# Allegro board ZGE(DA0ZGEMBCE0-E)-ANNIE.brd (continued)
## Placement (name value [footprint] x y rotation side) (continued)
CG570  0.47u/6.3V_2  [C0201]  64.07 113.05 90 bottom
CG571  0.47u/6.3V_2  [C0201]  62.64 113.05 270 bottom
CG572  0.47u/6.3V_2  [C0201]  63.36 113.05 90 bottom
CG573  0.47u/6.3V_2  [C0201]  61.93 113.05 270 bottom
CG574  0.47u/6.3V_2  [C0201]  22.87 113.01 180 bottom
CG575  330u/2V_7343H1.9  [CC7343]  83.44 112.99 90 bottom
CG576  0.47u/6.3V_2  [C0201]  56.79 112.93 0 bottom
CG577  0.47u/6.3V_2  [C0201]  21.84 112.87 270 bottom
CG578  47u/6.3V_8  [C0805]  59.22 112.81 180 bottom
CG579  0.47u/6.3V_2  [C0201]  66.09 112.65 180 bottom
CG580  0.47u/6.3V_2  [C0201]  55.48 112.56 0 bottom
CG581  0.47u/6.3V_2  [C0201]  65.11 112.52 180 bottom
CG582  0.47u/6.3V_2  [C0201]  44.72 112.3 180 bottom
CG583  0.47u/6.3V_2  [C0201]  14.06 112.16 180 bottom
CG584  0.47u/6.3V_2  [C0201]  24.5 111.99 270 bottom
CG585  10u/6.3V_6  [C0603]  99.17 111.98 0 bottom
CG586  0.47u/6.3V_2  [C0201]  9.92 111.87 270 bottom
CG587  22u/6.3V_6  [C0603]  8.65 111.85 90 bottom
CG588  0.47u/6.3V_2  [C0201]  87.72 111.73 0 bottom
CG589  0.47u/6.3V_2  [C0201]  95.55 111.71 180 bottom
CG590  0.47u/6.3V_2  [C0201]  47.61 111.7 270 bottom
CG591  0.47u/6.3V_2  [C0201]  46.89 111.7 90 bottom
CG592  0.47u/6.3V_2  [C0201]  46.15 111.7 270 bottom
CG593  0.47u/6.3V_2  [C0201]  96.93 111.7 0 bottom
CG594  0.47u/6.3V_2  [C0201]  48.32 111.7 270 bottom
CG595  0.47u/6.3V_2  [C0201]  51.89 111.7 270 bottom
CG596  0.47u/6.3V_2  [C0201]  49.75 111.7 90 bottom
CG597  0.47u/6.3V_2  [C0201]  51.18 111.7 90 bottom
CG598  0.47u/6.3V_2  [C0201]  50.46 111.7 270 bottom
CG599  0.47u/6.3V_2  [C0201]  49.04 111.7 90 bottom
CG600  0.47u/6.3V_2  [C0201]  52.61 111.7 90 bottom
CG601  0.47u/6.3V_2  [C0201]  53.33 111.69 270 bottom
CG602  0.47u/6.3V_2  [C0201]  63.71 111.68 270 bottom
CG603  0.47u/6.3V_2  [C0201]  63 111.68 270 bottom
CG604  0.47u/6.3V_2  [C0201]  62.28 111.68 90 bottom
CG605  0.47u/6.3V_2  [C0201]  61.57 111.68 90 bottom
CG606  0.47u/6.3V_2  [C0201]  54.04 111.68 270 bottom
CG607  0.47u/6.3V_2  [C0201]  55.47 111.68 270 bottom
CG608  0.47u/6.3V_2  [C0201]  54.76 111.68 90 bottom
CG609  0.47u/6.3V_2  [C0201]  56.18 111.67 90 bottom
CG610  0.47u/6.3V_2  [C0201]  56.9 111.65 90 bottom
CG611  0.47u/6.3V_2  [C0201]  19.59 111.62 270 bottom
CG612  0.47u/6.3V_2  [C0201]  14.95 111.6 270 bottom
CG613  0.47u/6.3V_2  [C0201]  57.76 111.47 180 bottom
CG614  0.47u/6.3V_2  [C0201]  59.73 111.46 180 bottom
CG615  0.47u/6.3V_2  [C0201]  58.74 111.46 0 bottom
CG616  0.47u/6.3V_2  [C0201]  60.72 111.46 0 bottom
CG617  10u/6.3V_6  [C0603]  65.38 111.3 0 bottom
CG618  22u/6.3V_6  [C0603]  44.19 111.22 180 bottom
CG619  0.47u/6.3V_2  [C0201]  89.41 111.12 0 bottom
CG620  0.47u/6.3V_2  [C0201]  18.12 111.01 180 bottom
CG621  0.47u/6.3V_2  [C0201]  90.93 110.94 180 bottom
CG622  0.47u/6.3V_2  [C0201]  86.35 110.91 0 bottom
CG623  22u/6.3V_6  [C0603]  25.44 110.76 0 bottom
CG624  0.47u/6.3V_2  [C0201]  99.95 110.61 270 bottom
CG625  0.47u/6.3V_2  [C0201]  49.27 110.31 270 bottom
CG626  0.47u/6.3V_2  [C0201]  48.55 110.3 90 bottom
CG627  0.47u/6.3V_2  [C0201]  60.95 110.3 90 bottom
CG628  0.47u/6.3V_2  [C0201]  49.99 110.29 270 bottom
CG629  0.47u/6.3V_2  [C0201]  60.24 110.29 90 bottom
CG630  10u/6.3V_6  [C0603]  46.87 110.29 0 bottom
CG631  0.47u/6.3V_2  [C0201]  59.53 110.29 270 bottom
CG632  0.47u/6.3V_2  [C0201]  58.81 110.29 270 bottom
CG633  10u/6.3V_6  [C0603]  51.67 110.29 180 bottom
CG634  0.47u/6.3V_2  [C0201]  55.48 110.27 90 bottom
CG635  0.47u/6.3V_2  [C0201]  54.76 110.27 270 bottom
CG636  10u/6.3V_6  [C0603]  62.62 110.27 0 bottom
CG637  0.47u/6.3V_2  [C0201]  53.34 110.27 90 bottom
CG638  0.47u/6.3V_2  [C0201]  54.05 110.27 90 bottom
CG639  10u/6.3V_6  [C0603]  57.15 110.26 0 bottom
CG640  0.47u/6.3V_2  [C0201]  66.65 110.24 180 bottom
CG641  0.47u/6.3V_2  [C0201]  65.2 110.23 180 bottom
CG642  0.47u/6.3V_2  [C0201]  44.94 110.16 180 bottom
CG643  0.47u/6.3V_2  [C0201]  43.6 110.15 0 bottom
CG644  22u/6.3V_6  [C0603]  72.17 109.48 270 bottom
CG645  0.47u/6.3V_2  [C0201]  18.79 109.47 0 bottom
CG646  0.47u/6.3V_2  [C0201]  44.95 109.44 180 bottom
CG647  0.47u/6.3V_2  [C0201]  43.6 109.43 0 bottom
CG648  0.47u/6.3V_2  [C0201]  23.81 109.4 90 bottom
CG649  10u/6.3V_6  [C0603]  65.36 109.17 180 bottom
CG650  0.47u/6.3V_2  [C0201]  45.85 108.91 90 bottom
CG651  0.47u/6.3V_2  [C0201]  47.99 108.91 90 bottom
CG652  0.47u/6.3V_2  [C0201]  47.27 108.91 270 bottom
CG653  0.47u/6.3V_2  [C0201]  48.7 108.91 270 bottom
CG654  0.47u/6.3V_2  [C0201]  55.84 108.91 90 bottom
CG655  0.47u/6.3V_2  [C0201]  52.99 108.91 90 bottom
CG656  0.47u/6.3V_2  [C0201]  46.56 108.91 270 bottom
CG657  0.47u/6.3V_2  [C0201]  55.13 108.91 90 bottom
CG658  0.47u/6.3V_2  [C0201]  54.41 108.91 270 bottom
CG659  0.47u/6.3V_2  [C0201]  53.7 108.91 270 bottom
CG660  0.47u/6.3V_2  [C0201]  57.27 108.91 270 bottom
CG661  0.47u/6.3V_2  [C0201]  56.55 108.91 90 bottom
CG662  0.47u/6.3V_2  [C0201]  52.27 108.91 270 bottom
CG663  0.47u/6.3V_2  [C0201]  51.56 108.91 90 bottom
CG664  0.47u/6.3V_2  [C0201]  60.12 108.9 270 bottom
CG665  0.47u/6.3V_2  [C0201]  59.41 108.9 270 bottom
CG666  0.47u/6.3V_2  [C0201]  50.85 108.9 270 bottom
CG667  0.47u/6.3V_2  [C0201]  58.7 108.9 90 bottom
CG668  0.47u/6.3V_2  [C0201]  57.98 108.9 270 bottom
CG669  0.47u/6.3V_2  [C0201]  49.42 108.9 270 bottom
CG670  0.47u/6.3V_2  [C0201]  50.14 108.9 90 bottom
CG671  0.47u/6.3V_2  [C0201]  63.69 108.9 270 bottom
CG672  0.47u/6.3V_2  [C0201]  62.97 108.9 270 bottom
CG673  0.47u/6.3V_2  [C0201]  62.26 108.9 90 bottom
CG674  0.47u/6.3V_2  [C0201]  61.54 108.9 270 bottom
CG675  0.47u/6.3V_2  [C0201]  60.83 108.9 270 bottom
CG676  0.47u/6.3V_2  [C0201]  90.87 108.86 180 bottom
CG677  0.47u/6.3V_2  [C0201]  14.23 108.7 0 bottom
CG678  0.47u/6.3V_2  [C0201]  18.78 108.58 0 bottom
CG679  10u/6.3V_6  [C0603]  26.79 108.58 90 bottom
CG680  10u/6.3V_6  [C0603]  24.66 108.14 180 bottom
CG681  0.47u/6.3V_2  [C0201]  65.13 108.11 180 bottom
CG682  0.47u/6.3V_2  [C0201]  90.14 108.09 0 bottom
CG683  0.47u/6.3V_2  [C0201]  22.77 108.08 180 bottom
CG684  0.47u/6.3V_2  [C0201]  20.82 108.08 0 bottom
CG685  0.47u/6.3V_2  [C0201]  94.82 108.07 90 bottom
CG686  0.47u/6.3V_2  [C0201]  15.49 108.07 180 bottom
CG687  0.47u/6.3V_2  [C0201]  12.37 108.05 0 bottom
CG688  0.47u/6.3V_2  [C0201]  10.73 108 0 bottom
CG689  47u/6.3V_8  [C0805]  43.88 107.82 0 bottom
CG690  1u/6.3V_2  [C0201]  84.83 107.66 270 bottom
CG691  0.47u/6.3V_2  [C0201]  99.62 107.54 90 bottom
CG692  10u/6.3V_6  [C0603]  47.63 107.51 0 bottom
CG693  0.47u/6.3V_2  [C0201]  59.7 107.5 270 bottom
CG694  0.47u/6.3V_2  [C0201]  58.98 107.5 90 bottom
CG695  10u/6.3V_6  [C0603]  53.12 107.49 180 bottom
CG696  0.47u/6.3V_2  [C0201]  49.3 107.48 90 bottom
CG697  0.47u/6.3V_2  [C0201]  50.02 107.48 270 bottom
CG698  0.47u/6.3V_2  [C0201]  45.94 107.47 270 bottom
CG699  0.47u/6.3V_2  [C0201]  50.73 107.46 90 bottom
CG700  0.47u/6.3V_2  [C0201]  51.44 107.45 270 bottom
CG701  0.47u/6.3V_2  [C0201]  97.9 107.34 180 bottom
CG702  *820p/50V_4  [C0402]  17.21 107.18 180 bottom
CG703  10u/6.3V_6  [C0603]  65.28 107.04 180 bottom
CG704  10u/6.3V_6  [C0603]  11.75 106.9 180 bottom
CG705  10u/6.3V_6  [C0603]  56.2 106.73 90 bottom
CG706  10u/6.3V_6  [C0603]  57.62 106.73 90 bottom
CG707  0.47u/6.3V_2  [C0201]  86.93 106.71 0 bottom
CG708  *22u/6.3V_6  [C0603]  62.87 106.58 270 bottom
CG709  *22u/6.3V_6  [C0603]  61.04 106.58 270 bottom
CG710  0.47u/6.3V_2  [C0201]  43.7 106.42 0 bottom
CG711  0.47u/6.3V_2  [C0201]  97.38 106.34 90 bottom
CG712  0.47u/6.3V_2  [C0201]  88.06 106.33 90 bottom
CG713  2.2u/10V_4  [C0402]  24.58 106.16 90 bottom
CG714  0.47u/6.3V_2  [C0201]  54.08 106.11 90 bottom
CG715  0.47u/6.3V_2  [C0201]  53.36 106.11 270 bottom
CG716  0.47u/6.3V_2  [C0201]  52.64 106.11 90 bottom
CG717  0.47u/6.3V_2  [C0201]  47.87 106.11 90 bottom
CG718  0.47u/6.3V_2  [C0201]  48.58 106.11 90 bottom
CG719  0.47u/6.3V_2  [C0201]  49.3 106.1 270 bottom
CG720  0.47u/6.3V_2  [C0201]  59.7 106.1 90 bottom
CG721  0.47u/6.3V_2  [C0201]  58.98 106.1 270 bottom
CG722  22u/6.3V_6  [C0603]  50.97 106.07 0 bottom
CG723  0.47u/6.3V_2  [C0201]  96.38 105.99 90 bottom
CG724  0.47u/6.3V_2  [C0201]  64.59 105.98 180 bottom
CG725  47u/6.3V_8  [C0805]  45.89 105.72 180 bottom
CG726  22u/6.3V_6  [C0603]  99.3 105.71 270 bottom
CG727  4.7u/6.3V_6  [C0603]  86.2 105.64 180 bottom
CG728  0.47u/6.3V_2  [C0201]  43.78 105.61 0 bottom
CG729  0.1u/16V_4  [C0402]  18.14 105.18 0 bottom
CG730  0.47u/6.3V_2  [C0201]  97.95 104.91 180 bottom
CG731  10u/6.3V_6  [C0603]  65.27 104.9 0 bottom
CG732  0.47u/6.3V_2  [C0201]  59.7 104.7 270 bottom
CG733  0.47u/6.3V_2  [C0201]  58.98 104.7 90 bottom
CG734  0.47u/6.3V_2  [C0201]  93.02 104.48 270 bottom
CG735  0.47u/6.3V_2  [C0201]  96.34 104.33 270 bottom
CG736  47u/6.3V_8  [C0805]  49.3 104.3 0 bottom
CG737  4.7u/6.3V_6  [C0603]  39.24 104.17 90 bottom
CG738  10u/6.3V_6  [C0603]  37.61 104.17 90 bottom
CG739  4.7u/6.3V_6  [C0603]  40.67 104.15 270 bottom
CG740  0.47u/6.3V_2  [C0201]  87.58 104.15 0 bottom
CG741  0.47u/6.3V_2  [C0201]  46.6 104.02 270 bottom
CG742  0.47u/6.3V_2  [C0201]  47.32 104.02 270 bottom
CG743  0.47u/6.3V_2  [C0201]  45.89 104.02 90 bottom
CG744  0.47u/6.3V_2  [C0201]  19.07 103.8 0 bottom
CG745  0.47u/6.3V_2  [C0201]  99.74 103.79 270 bottom
CG746  0.47u/6.3V_2  [C0201]  64.39 103.69 270 bottom
CG747  0.47u/6.3V_2  [C0201]  90.93 103.65 0 bottom
CG748  0.47u/6.3V_2  [C0201]  89.96 103.62 270 bottom
CG749  10u/6.3V_6  [C0603]  62.53 103.57 90 bottom
CG750  22u/6.3V_6  [C0603]  61.09 103.57 90 bottom
CG751  10u/6.3V_6  [C0603]  56.2 103.57 270 bottom
CG752  10u/6.3V_6  [C0603]  57.62 103.56 270 bottom
CG753  0.47u/6.3V_2  [C0201]  84.75 103.37 90 bottom
CG754  0.47u/6.3V_2  [C0201]  59.7 103.3 270 bottom
CG755  0.47u/6.3V_2  [C0201]  58.98 103.3 90 bottom
CG756  22u/6.3V_6  [C0603]  43.4 103.13 90 bottom
CG757  4.7u/6.3V_6  [C0603]  44.82 103.13 270 bottom
CG758  10u/6.3V_6  [C0603]  65.34 102.77 225 bottom
CG759  0.47u/6.3V_2  [C0201]  52.64 102.61 90 bottom
CG760  0.47u/6.3V_2  [C0201]  51.93 102.61 90 bottom
CG761  0.47u/6.3V_2  [C0201]  51.22 102.61 270 bottom
CG762  0.47u/6.3V_2  [C0201]  48.36 102.61 90 bottom
CG763  0.47u/6.3V_2  [C0201]  47.65 102.61 270 bottom
CG764  0.47u/6.3V_2  [C0201]  53.36 102.61 90 bottom
CG765  0.47u/6.3V_2  [C0201]  50.5 102.6 270 bottom
CG766  0.47u/6.3V_2  [C0201]  49.07 102.6 270 bottom
CG767  0.47u/6.3V_2  [C0201]  54.08 102.6 270 bottom
CG768  0.47u/6.3V_2  [C0201]  49.79 102.6 90 bottom
CG769  0.47u/6.3V_2  [C0201]  46.93 102.6 90 bottom
CG770  0.47u/6.3V_2  [C0201]  46.22 102.6 90 bottom
CG771  4.7u/6.3V_6  [C0603]  20.92 103.06 0 bottom
CG772  0.47u/6.3V_2  [C0201]  58.95 102.03 0 bottom
CG773  4.7u/6.3V_6  [C0603]  20.82 101.03 90 bottom
CG774  0.47u/6.3V_2  [C0201]  24.35 101.77 270 bottom
CG775  0.47u/6.3V_2  [C0201]  23.62 101.77 270 bottom
CG776  10u/6.3V_6  [C0603]  66.36 101.75 225 bottom
CG777  0.47u/6.3V_2  [C0201]  23.3 100.13 0 bottom
CG778  0.47u/6.3V_2  [C0201]  44.2 101.44 0 bottom
CG779  2.2u/10V_4  [C0402]  42.22 101.2 180 bottom
CG780  0.47u/6.3V_2  [C0201]  57.2 101.17 270 bottom
CG781  0.47u/6.3V_2  [C0201]  57.91 101.17 270 bottom
CG782  0.47u/6.3V_2  [C0201]  56.48 101.17 270 bottom
CG783  0.47u/6.3V_2  [C0201]  58.62 101.17 270 bottom
CG784  0.47u/6.3V_2  [C0201]  55.77 101.17 270 bottom
CG785  0.47u/6.3V_2  [C0201]  59.33 101.16 270 bottom
CG786  0.47u/6.3V_2  [C0201]  55.05 101.16 270 bottom
CG787  0.47u/6.3V_2  [C0201]  60.76 101.16 90 bottom
CG788  0.47u/6.3V_2  [C0201]  54.34 101.16 270 bottom
CG789  0.47u/6.3V_2  [C0201]  60.05 101.16 270 bottom
CG790  1u/6.3V_2  [C0201]  45.78 101.16 270 bottom
CG791  0.47u/6.3V_2  [C0201]  45.06 101.16 270 bottom
CG792  0.47u/6.3V_2  [C0201]  46.49 101.16 90 bottom
CG793  0.47u/6.3V_2  [C0201]  51.48 101.16 90 bottom
CG794  0.47u/6.3V_2  [C0201]  52.91 101.16 90 bottom
CG795  0.47u/6.3V_2  [C0201]  61.48 101.16 90 bottom
CG796  0.47u/6.3V_2  [C0201]  53.62 101.16 90 bottom
CG797  0.47u/6.3V_2  [C0201]  52.2 101.16 270 bottom
CG798  0.47u/6.3V_2  [C0201]  62.19 101.16 90 bottom
CG799  0.47u/6.3V_2  [C0201]  50.77 101.16 90 bottom
CG800  0.47u/6.3V_2  [C0201]  50.05 101.16 270 bottom
CG801  0.47u/6.3V_2  [C0201]  49.34 101.16 90 bottom
CG802  0.47u/6.3V_2  [C0201]  48.63 101.16 90 bottom
CG803  0.47u/6.3V_2  [C0201]  47.92 101.16 90 bottom
CG804  0.47u/6.3V_2  [C0201]  47.2 101.16 90 bottom
CG805  0.47u/6.3V_2  [C0201]  99.71 101.15 90 bottom
CG806  0.47u/6.3V_2  [C0201]  85.06 101.02 90 bottom
CG807  4.7u/6.3V_6  [C0603]  63.25 100.95 270 bottom
CG808  10u/6.3V_6  [C0603]  67.4 100.69 225 bottom
CG809  0.47u/6.3V_2  [C0201]  61.99 100.3 180 bottom
CG810  0.47u/6.3V_2  [C0201]  60.99 100.26 180 bottom
CG811  0.47u/6.3V_2  [C0201]  17.87 101.49 90 bottom
CG812  10u/6.3V_6  [C0603]  68.78 100.05 225 bottom
CG813  0.47u/6.3V_2  [C0201]  43.22 100.04 270 bottom
CG814  0.47u/6.3V_2  [C0201]  43.93 100.04 270 bottom
CG815  0.47u/6.3V_2  [C0201]  59.71 100.03 0 bottom
CG816  0.47u/6.3V_2  [C0201]  89.43 99.96 0 bottom
CG817  0.47u/6.3V_2  [C0201]  86.1 99.94 0 bottom
CG818  0.47u/6.3V_2  [C0201]  98.58 99.93 180 bottom
CG819  0.47u/6.3V_2  [C0201]  95.56 99.93 180 bottom
CG820  0.47u/6.3V_2  [C0201]  97.07 99.93 180 bottom
CG821  0.47u/6.3V_2  [C0201]  87.58 99.93 0 bottom
CG822  0.47u/6.3V_2  [C0201]  94.32 99.9 0 bottom
CG823  0.47u/6.3V_2  [C0201]  88.51 99.8 270 bottom
CG824  0.47u/6.3V_2  [C0201]  52.26 99.79 270 bottom
CG825  0.47u/6.3V_2  [C0201]  51.54 99.79 90 bottom
CG826  0.47u/6.3V_2  [C0201]  50.83 99.79 90 bottom
CG827  0.47u/6.3V_2  [C0201]  50.12 99.79 90 bottom
CG828  0.47u/6.3V_2  [C0201]  49.41 99.79 270 bottom
CG829  0.47u/6.3V_2  [C0201]  48.7 99.79 270 bottom
CG830  0.47u/6.3V_2  [C0201]  47.98 99.79 90 bottom
CG831  0.47u/6.3V_2  [C0201]  47.27 99.79 90 bottom
CG832  22u/6.3V_6  [C0603]  54.93 99.77 0 bottom
CG833  0.47u/6.3V_2  [C0201]  53.25 99.76 270 bottom
CG834  4.7u/6.3V_6  [C0603]  45.6 99.76 180 bottom
CG835  *820p/50V_4  [C0402]  92.68 99.7 180 bottom
CG836  0.47u/6.3V_2  [C0201]  63.04 99.28 180 bottom
CG837  4.7u/6.3V_6  [C0603]  58.31 99.23 270 bottom
CG838  0.47u/6.3V_2  [C0201]  43.35 99.18 0 bottom
CG839  0.47u/6.3V_2  [C0201]  59.96 99.1 270 bottom
CG840  4.7u/6.3V_6  [C0603]  19.06 98.97 180 bottom
CG841  0.47u/6.3V_2  [C0201]  60.77 99.03 90 bottom
CG842  10u/6.3V_6  [C0603]  64.62 99.01 45 bottom
CG843  10u/6.3V_6  [C0603]  69.83 98.97 225 bottom
CG844  0.47u/6.3V_2  [C0201]  52.06 98.9 0 bottom
CG845  0.47u/6.3V_2  [C0201]  67.57 98.78 315 bottom
CG846  0.47u/6.3V_2  [C0201]  54.05 98.47 0 bottom
CG847  0.47u/6.3V_2  [C0201]  43.35 98.45 180 bottom
CG848  0.47u/6.3V_2  [C0201]  57.04 98.44 90 bottom
CG849  4.7u/6.3V_6  [C0603]  61.84 98.39 90 bottom
CG850  0.47u/6.3V_2  [C0201]  55.72 98.38 90 bottom
CG851  0.47u/6.3V_2  [C0201]  55.01 98.38 90 bottom
CG852  10u/6.3V_6  [C0603]  71.16 98.28 225 bottom
CG853  0.47u/6.3V_2  [C0201]  68.3 98.09 135 bottom
CG854  10u/6.3V_6  [C0603]  65.64 97.99 45 bottom
CG855  0.47u/6.3V_2  [C0201]  54.05 97.75 0 bottom
CG856  4.7u/6.3V_6  [C0603]  46.41 97.67 90 bottom
CG857  *22u/6.3V_6  [C0603]  72.17 97.28 225 bottom
CG858  0.47u/6.3V_2  [C0201]  50.62 97.2 0 bottom
CG859  10u/6.3V_6  [C0603]  66.65 97 45 bottom
CG860  0.47u/6.3V_2  [C0201]  72.99 96.58 225 bottom
CG861  10u/6.3V_6  [C0603]  69.32 96.4 45 bottom
CG862  22u/6.3V_6  [C0603]  48.48 95.77 90 bottom
CG863  0.22u/6.3V_2  [C0201]  67.33 95.6 180 bottom
CG864  *22u/6.3V_6  [C0603]  70.35 95.4 45 bottom
CG865  *47p/50V_4  [C0402]  42.17 94.9 270 bottom
CG866  0.22u/6.3V_2  [C0201]  67.33 94.83 180 bottom
CG867  0.22u/6.3V_2  [C0201]  97.76 93.85 180 bottom
CG868  0.22u/6.3V_2  [C0201]  68.6 93.44 180 bottom
CG869  *47p/50V_4  [C0402]  43.58 93.26 270 bottom
CG870  0.22u/6.3V_2  [C0201]  97.76 93.09 180 bottom
CG871  0.22u/6.3V_2  [C0201]  67.12 92.87 90 bottom
CG872  0.22u/6.3V_2  [C0201]  66.36 92.87 90 bottom
CG873  0.22u/6.3V_2  [C0201]  65.47 92.87 90 bottom
CG874  0.22u/6.3V_2  [C0201]  64.71 92.87 90 bottom
CG875  0.22u/6.3V_2  [C0201]  63.87 92.87 90 bottom
CG876  0.22u/6.3V_2  [C0201]  63.11 92.87 90 bottom
CG877  0.22u/6.3V_2  [C0201]  68.6 92.67 180 bottom
CG878  0.22u/6.3V_2  [C0201]  97.79 92.23 180 bottom
CG879  0.22u/6.3V_2  [C0201]  97.79 91.47 180 bottom
CG880  0.22u/6.3V_2  [C0201]  97.78 90.72 180 bottom
CG881  0.22u/6.3V_2  [C0201]  97.78 89.96 180 bottom
CG882  0.22u/6.3V_2  [C0201]  67.61 84.29 180 bottom
CG883  0.22u/6.3V_2  [C0201]  60.57 84.24 90 bottom
CG884  0.22u/6.3V_2  [C0201]  59.43 84.24 90 bottom
CG885  0.22u/6.3V_2  [C0201]  58.67 84.24 90 bottom
CG886  0.22u/6.3V_2  [C0201]  57.52 84.24 90 bottom
CG887  0.22u/6.3V_2  [C0201]  56.76 84.24 90 bottom
CG888  0.22u/6.3V_2  [C0201]  55.36 84.24 90 bottom
CG889  0.22u/6.3V_2  [C0201]  54.6 84.24 90 bottom
CG890  0.22u/6.3V_2  [C0201]  53.21 84.24 90 bottom
CG891  0.22u/6.3V_2  [C0201]  52.4 84.24 90 bottom
CG892  0.22u/6.3V_2  [C0201]  61.28 84.21 90 bottom
CG893  0.1u/16V_4  [C0402]  51.07 84.12 0 bottom
CG894  0.22u/6.3V_2  [C0201]  67.59 83.58 180 bottom
CG895  0.22u/6.3V_2  [C0201]  56.38 83.09 90 bottom
CG896  0.22u/6.3V_2  [C0201]  55.62 83.09 90 bottom
CG897  0.22u/6.3V_2  [C0201]  54.22 83.09 90 bottom
CG898  0.22u/6.3V_2  [C0201]  53.46 83.09 90 bottom
CG899  820p/50V_4  [C0402]  33.07 82.38 270 bottom
CG900  0.1u/16V_4  [C0402]  43.45 77.92 180 bottom
CG901  330u/2V_7343H1.9  [CC7343]  76.27 70.2 270 bottom
CG902  330u/2V_7343H1.9  [CC7343]  84.73 82.72 90 top
CG903  330u/2V_7343H1.9  [CC7343]  85.8 70.18 270 bottom
CN1  HDM-020-1S19HG  [HDMI-HDM-020-1S19HG-19P]  63.05 175.71 180 top
CN2  2DT1517-321211F  [DP-2DT1517-321211F-20P]  86.9 173.68 180 top
CN3  UCF3T-40N30-0P00  [UB31-UCF3T-40N30-0P00-24P-TBT]  294.95 42.3 90 top
CN4  MJ8E0B-T880-422  [UB31-MJ8E0B-T880-422-24P]  291.5 27.95 90 top
CN5  *APS CONN  [88511-180N-18P-L]  228.36 11.85 0 top
CN6  50273-0020N-V09  [50273-0020N-V09-2P-L]  240.6 11.8 0 top
CN7  2UB4006-152101F  [UB3-2UB4006-157101F-9P]  293.85 11.7 90 top
CN8  51619-0180N-001  [51619-0180N-001-18P-L]  33.1 163.95 0 bottom
CN9  51619-0080N-001  [51619-0080N-001-8P-L]  17.9 163.55 0 bottom
CN10  GS12401-1011P-7H  [GS12401-1011-9H-40P-R]  176.95 122 270 bottom
CN11  50271-0040N-V01  [50271-0040N-V01-4P-L]  10.4 66.8 0 bottom
CN12  50271-0040N-V01  [50271-0040N-V01-4P-L]  201.2 61.5 270 bottom
CN13  50281-00401-001_Header  [WTB-50281-00401-001-4P-L]  16.2 57.9 90 bottom
CN14  50224-00801-001  [50224-00801-001-8P-L]  9.1 44.5 90 bottom
CN15  NASM0-S6701-TS40  [NGFF-NASM0-S6701-TS40-75P-KM]  194.85 43.75 270 bottom
CN16  NASE0-S6701-TSH4  [NGFF-NASE0-S6701-TSH4-KE-SMT]  52.15 42 90 bottom
CN17  51695-0450M-V01  [FPC-51695-0450M-V01-45P-L]  8.9 25 90 bottom
CN18  NASM0-S6701-TS40  [NGFF-NASM0-S6701-TS40-75P-KM]  194.85 18.7 270 bottom
CN19  51540-04401-V01  [51540-04401-V01-44P-L]  77.9 16.05 180 bottom
CN20  HDD@GS12201-1011-7H  [WTB-GS12201-1011-7H-20P-L-SMT]  30.9 15.25 180 bottom
CN21  51288-0060N-001  [51288-0060N-001-6P-L]  56.3 15.4 180 bottom
CN22  50271-00201-001  [50271-00201-001-2P-L]  18.9 15.5 180 bottom
D1  *PESD5V0H1BSF  [D-0_6X0_3-0_32H-SMT]  87.75 161.21 270 top
D2  *PESD5V0H1BSF  [D-0_6X0_3-0_32H-SMT]  88.9 161.21 270 top
D3  *PESD5V0H1BSF  [D-0_6X0_3-0_32H-SMT]  92.27 161.2 270 top
D4  *PESD5V0H1BSF  [D-0_6X0_3-0_32H-SMT]  93.49 161.2 270 top
D5  *PESD5V0H1BSF  [D-0_6X0_3-0_32H-SMT]  94.56 161.18 270 top
D6  *PESD5V0H1BSF  [D-0_6X0_3-0_32H-SMT]  95.78 161.18 270 top
D7  *PESD5V0H1BSF  [D-0_6X0_3-0_32H-SMT]  89.93 161.17 270 top
D8  *PESD5V0H1BSF  [D-0_6X0_3-0_32H-SMT]  91.1 161.17 270 top
D9  *AZ5725-01F.R7G  [ESD-1X0_6-2P]  37.51 160.51 270 top
D10  *AZ5725-01F.R7G  [ESD-1X0_6-2P]  177.84 127.63 180 top
D11  *AZ5725-01F.R7G  [ESD-1X0_6-2P]  177.84 126.28 180 top
D12  *AZ5725-01F.R7G  [ESD-1X0_6-2P]  178.45 124.76 90 top
D13  *AZ5725-01F.R7G  [ESD-1X0_6-2P]  178.45 122.85 270 top
D14  SDM20U30-7  [D-1_2X0_8-0_7H]  178.45 118.41 0 top
D15  *SBR3U40P1-7  [D-2_8X1_78]  12.97 66.59 270 top
D16  *AZ5725-01F.R7G  [ESD-1X0_6-2P]  10.81 61.26 270 top
D17  *AZ5725-01F.R7G  [ESD-1X0_6-2P]  10.43 59.73 0 top
D18  RB500V-40  [D-SOD323-1_85X1_25-0_95H]  255.28 59.22 180 top
D19  *AZ5725-01F.R7G  [ESD-1X0_6-2P]  10.43 58.59 0 top
D20  *AZ5725-01F.R7G  [ESD-1X0_6-2P]  11.6 55.52 270 top
D21  PESD5V0H1BSF  [D-0_6X0_3-0_32H-SMT]  287.18 47.16 0 top
D22  PESD5V0H1BSF  [D-0_6X0_3-0_32H-SMT]  288.44 47.16 180 top
D23  PESD5V0H1BSF  [D-0_6X0_3-0_32H-SMT]  290.13 46.65 270 top
D24  PESD5V0H1BSF  [D-0_6X0_3-0_32H-SMT]  287.57 45.13 270 top
D25  PESD5V0H1BSF  [D-0_6X0_3-0_32H-SMT]  287.57 43.73 90 top
D26  PESD5V0H1BSF  [D-0_6X0_3-0_32H-SMT]  286.3 42.84 270 top
D27  PESD5V0H1BSF  [D-0_6X0_3-0_32H-SMT]  286.3 41.57 90 top
D28  PESD5V0H1BSF  [D-0_6X0_3-0_32H-SMT]  290.14 40.9 90 top
D29  PESD5V0H1BSF  [D-0_6X0_3-0_32H-SMT]  287.57 40.81 270 top
D30  PESD5V0H1BSF  [D-0_6X0_3-0_32H-SMT]  287.57 39.41 90 top
D31  AZ5725-01F.R7G  [ESD-1X0_6-2P]  73.54 39.1 0 top
D32  RB500V-40  [D-SOD323-1_85X1_25-0_95H]  27.32 38.4 0 top
D33  *SDM20U30-7  [D-1_2X0_8-0_7H]  59.56 37.99 90 top
D34  PESD5V0H1BSF  [D-0_6X0_3-0_32H-SMT]  287.29 37.53 270 top
D35  SDM20U30-7  [D-1_2X0_8-0_7H]  60.98 36.98 90 top
D36  RB500V-40  [D-SOD323-1_85X1_25-0_95H]  27.32 36.87 0 top
D37  *SDM20U30-7  [D-1_2X0_8-0_7H]  56.41 37.18 90 top
D38  *SDM20U30-7  [D-1_2X0_8-0_7H]  57.91 37.18 90 top
D39  PESD5V0H1BSF  [D-0_6X0_3-0_32H-SMT]  287.29 36.23 90 top
D40  AZ5725-01F.R7G  [ESD-1X0_6-2P]  67.08 35.99 0 top
D41  PESD5V0H1BSF  [D-0_6X0_3-0_32H-SMT]  290.98 35.47 270 top
D42  PESD5V0H1BSF  [D-0_6X0_3-0_32H-SMT]  291.99 35.47 270 top
D43  AZ5725-01F.R7G  [ESD-1X0_6-2P]  23.26 35.12 180 top
D44  RB500V-40  [D-SOD323-1_85X1_25-0_95H]  63.4 34.67 180 top
D45  PESD5V0H1BSF  [D-0_6X0_3-0_32H-SMT]  288.94 34.2 270 top
D46  PESD5V0H1BSF  [D-0_6X0_3-0_32H-SMT]  286.27 34.08 270 top
D47  PESD5V0H1BSF  [D-0_6X0_3-0_32H-SMT]  286.27 32.81 90 top
D48  PESD5V0H1BSF  [D-0_6X0_3-0_32H-SMT]  288.94 32.81 90 top
D49  PESD5V0H1BSF  [D-0_6X0_3-0_32H-SMT]  230.9 32.17 180 top
D50  PESD5V0H1BSF  [D-0_6X0_3-0_32H-SMT]  287.57 31.05 270 top
D51  PESD5V0H1BSF  [D-0_6X0_3-0_32H-SMT]  287.58 29.75 90 top
D52  RB500V-40  [D-SOD323-1_85X1_25-0_95H]  12.85 21.12 0 top
D53  *AZ5725-01F.R7G  [ESD-1X0_6-2P]  84.98 19.14 180 top
D54  *AZ5725-01F.R7G  [ESD-1X0_6-2P]  86.84 19.13 0 top
D55  *AZ5725-01F.R7G  [ESD-1X0_6-2P]  85.11 17.57 180 top
D56  *AZ5725-01F.R7G  [ESD-1X0_6-2P]  97.81 17.82 90 top
D57  *AZ5725-01F.R7G  [ESD-1X0_6-2P]  87.65 17.31 180 top
D58  BAT54CW  [SOT23-1_7-65-3P]  235.98 17.06 270 top
D59  RB500V-40  [D-SOD323-1_85X1_25-0_95H]  10.53 16.78 0 top
D60  *AZ5725-01F.R7G  [ESD-1X0_6-2P]  68.09 16.68 90 top
D61  *AZ5725-01F.R7G  [ESD-1X0_6-2P]  69.11 16.68 90 top
D62  *AZ5725-01F.R7G  [ESD-1X0_6-2P]  70.12 16.68 90 top
D63  *AZ5725-01F.R7G  [ESD-1X0_6-2P]  71.14 16.68 90 top
D64  *AZ5725-01F.R7G  [ESD-1X0_6-2P]  72.15 16.68 90 top
D65  *AZ5725-01F.R7G  [ESD-1X0_6-2P]  73.17 16.68 90 top
D66  *AZ5725-01F.R7G  [ESD-1X0_6-2P]  74.19 16.68 90 top
D67  *AZ5725-01F.R7G  [ESD-1X0_6-2P]  75.2 16.68 90 top
D68  *AZ5725-01F.R7G  [ESD-1X0_6-2P]  76.22 16.68 90 top
D69  *AZ5725-01F.R7G  [ESD-1X0_6-2P]  77.23 16.68 90 top
D70  *AZ5725-01F.R7G  [ESD-1X0_6-2P]  78.25 16.68 90 top
D71  *AZ5725-01F.R7G  [ESD-1X0_6-2P]  79.27 16.68 90 top
D72  AZ5725-01F.R7G  [ESD-1X0_6-2P]  283.69 5.91 180 top
D73  *AZ5725-01F.R7G  [ESD-1X0_6-2P]  91.26 16.37 0 top
D74  *AZ5725-01F.R7G  [ESD-1X0_6-2P]  87.57 16.3 180 top
D75  *AZ5725-01F.R7G  [ESD-1X0_6-2P]  83.43 13.73 270 top
D76  PESD5V0H1BSF  [D-0_6X0_3-0_32H-SMT]  284.63 8.02 270 bottom
D77  1N4148WS  [D-SOD323-1_85X1_25-0_95H]  256.43 12.36 180 top
D78  PESD5V0H1BSF  [D-0_6X0_3-0_32H-SMT]  284.63 9.41 90 bottom
D79  1N4148WS  [D-SOD323-1_85X1_25-0_95H]  256.43 10.84 180 top
D80  PESD5V0H1BSF  [D-0_6X0_3-0_32H-SMT]  284.42 13.43 270 bottom
D81  PESD5V0H1BSF  [D-0_6X0_3-0_32H-SMT]  284.45 14.82 90 bottom
D82  *AZ5725-01F.R7G  [ESD-1X0_6-2P]  41.09 159.08 270 bottom
D83  *AZ5725-01F.R7G  [ESD-1X0_6-2P]  40.07 159.08 270 bottom
D84  *AZ5725-01F.R7G  [ESD-1X0_6-2P]  38.04 158.64 270 bottom
D85  *AZ5725-01F.R7G  [ESD-1X0_6-2P]  36.98 158.46 270 bottom
D86  *AZ5725-01F.R7G  [ESD-1X0_6-2P]  31.26 159.05 270 bottom
D87  *AZ5725-01F.R7G  [ESD-1X0_6-2P]  43.1 158.69 0 bottom
D88  *RB500V-40  [D-SOD323-1_85X1_25-0_95H]  20.97 158.28 90 bottom
D89  *AZ5725-01F.R7G  [ESD-1X0_6-2P]  19.2 71.16 0 bottom
D90  *AZ5725-01F.R7G  [ESD-1X0_6-2P]  19.2 70.15 0 bottom
D91  *AZ5725-01F.R7G  [ESD-1X0_6-2P]  19.2 69 0 bottom
D92  *AZ5725-01F.R7G  [ESD-1X0_6-2P]  19.2 67.99 0 bottom
D93  *AZ5725-01F.R7G  [ESD-1X0_6-2P]  19.2 66.97 0 bottom
D94  AZ4520-01F.R7G  [D-1_6X1]  286.4 49.44 90 bottom
D95  PESD5V0H1BSF  [D-0_6X0_3-0_32H-SMT]  287.57 45.13 270 bottom
D96  PESD5V0H1BSF  [D-0_6X0_3-0_32H-SMT]  287.57 43.73 90 bottom
D97  PESD5V0H1BSF  [D-0_6X0_3-0_32H-SMT]  287.57 40.81 270 bottom
D98  PESD5V0H1BSF  [D-0_6X0_3-0_32H-SMT]  287.57 39.41 90 bottom
D99  AZ4520-01F.R7G  [D-1_6X1]  285.9 36.69 180 bottom
D100  PESD5V0H1BSF  [D-0_6X0_3-0_32H-SMT]  288.94 34.2 270 bottom
D101  PESD5V0H1BSF  [D-0_6X0_3-0_32H-SMT]  286.58 33.21 270 bottom
D102  PESD5V0H1BSF  [D-0_6X0_3-0_32H-SMT]  288.94 32.81 90 bottom
D103  PESD5V0H1BSF  [D-0_6X0_3-0_32H-SMT]  286.58 31.94 90 bottom
D104  PESD5V0H1BSF  [D-0_6X0_3-0_32H-SMT]  287.75 31.04 270 bottom
D105  PESD5V0H1BSF  [D-0_6X0_3-0_32H-SMT]  287.76 29.75 90 bottom
D106  *SDM20U30-7  [D-1_2X0_8-0_7H]  66.74 26.02 90 bottom
D107  *AZ5725-01F.R7G  [ESD-1X0_6-2P]  85.06 24.15 180 bottom
D108  *AZ5725-01F.R7G  [ESD-1X0_6-2P]  85.06 22.83 180 bottom
D109  *AZ5725-01F.R7G  [ESD-1X0_6-2P]  73.83 21.4 90 bottom
D110  *AZ5725-01F.R7G  [ESD-1X0_6-2P]  85.11 21.63 180 bottom
D111  *AZ5725-01F.R7G  [ESD-1X0_6-2P]  77.08 20.72 0 bottom
D112  PESD5V0X2UM  [ESD3-0_985X0_585]  282.06 12.77 270 bottom
DG1  RB500V-40  [D-SOD323-1_85X1_25-0_95H]  30.24 102.4 270 top
DG2  SDM20U30-7  [D-1_2X0_8-0_7H]  21.48 101.06 0 top
DG3  RB500V-40  [D-SOD323-1_85X1_25-0_95H]  25.42 79.54 90 top
DG4  BAT54AW-L  [SOT23-1_7-65-3P]  41.65 78.53 0 top
DG5  RB500V-40  [D-SOD323-1_85X1_25-0_95H]  35.96 83.86 180 bottom
DG6  RB500V-40  [D-SOD323-1_85X1_25-0_95H]  43.83 81.71 180 bottom
DG7  RB500V-40  [D-SOD323-1_85X1_25-0_95H]  32.28 79.44 270 bottom
EC1  *10p/50V_4  [C0402]  165.96 126.15 0 top
EC2  10p/50V_4  [C0402]  104.94 101.4 0 top
EC3  *10P/50V/C0G_4  [C0402]  198.78 51.03 90 top
EC4  *10P/50V/C0G_4  [C0402]  202.46 49.95 0 top
EC5  *10P/50V/C0G_4  [C0402]  236.01 32.54 0 top
EC6  *10P/50V/C0G_4  [C0402]  211.98 19.51 270 top
EC7  *10p/50V_4  [C0402]  39.06 158.58 270 bottom
EC8  *10p/50V_4  [C0402]  235.6 38.78 0 bottom
EC9  *10P/50V/C0G_4  [C0402]  210.97 36.3 180 bottom
EC10  *10P/50V/C0G_4  [C0402]  203.6 29.38 180 bottom
EC11  *10p/50V_4  [C0402]  228.19 17.94 0 bottom
EC12  *10p/50V_4  [C0402]  227.73 14.27 0 bottom
ESD1  *AZ1045-04F.R7G  [ESD10-2_5X1-5-9P-AZ1143]  84.22 160.82 180 bottom
HOLE1  *hg-tic315bc394d118p2  [HG-TIC315BC394D118P2]  46.9 172.9 0 top
HOLE2  *hg-tic315bc394d118p2  [HG-TIC315BC394D118P2]  136.4 172.9 0 top
HOLE3  *2D-BARCODE-8X8-S  [2D-BARCODE-8X8-S]  160.29 171.36 180 top
HOLE4  *hg-c315d118p2  [HG-C315D118P2]  104.35 170.9 0 top
HOLE5  *hg-c315d118p2  [HG-C315D118P2]  179.3 141.9 0 top
HOLE6  *H-TIC220BC283D146P2  [H-TIC220BC283D146P2]  18.4 140.2 0 top
HOLE7  *H-TIC220BC283D146P2  [H-TIC220BC283D146P2]  91.3 140.2 0 top
HOLE8  *H-TIC220BC283D146P2  [H-TIC220BC283D146P2]  118.2 140 0 top
HOLE9  *H-TIC220BC283D146P2  [H-TIC220BC283D146P2]  165 140 0 top
HOLE10  *H-ZGE-1N  [H-ZGE-1N]  101.02 139.5 0 top
HOLE11  *H-TIC220BC283D146P2  [H-TIC220BC283D146P2]  118.2 99 0 top
HOLE12  *hg-tic315bc394d118p2  [HG-TIC315BC394D118P2]  182.9 11.85 0 top
HOLE13  *hg-c315d118p2  [HG-C315D118P2]  9.4 96 0 top
HOLE14  *H-TIC220BC283D146P2  [H-TIC220BC283D146P2]  18.4 81.9 0 top
HOLE15  *H-TIC220BC283D146P2  [H-TIC220BC283D146P2]  91.3 81.9 0 top
HOLE16  *hg-tic315bc394d118p2  [HG-TIC315BC394D118P2]  186.8 75.8 0 top
HOLE17  *hg-c315d118p2  [HG-C315D118P2]  245.9 58.5 0 top
HOLE18  *H-O114X102D114X102N  [H-O114X102D114X102N]  286.4 54.9 0 top
HOLE19  *hg-tic315bc394d118p2  [HG-TIC315BC394D118P2]  292.9 54.9 0 top
HOLE20  *H-C315D220P2  [H-C315D220P2]  93.4 43.9 0 top
HOLE21  -  [H-TC228BC181D138P2]  273.2 43.75 180 bottom
HOLE22  -  [H-TC228IBC181D130P2]  23.8 42 180 bottom
HOLE23  *H-C102D102N  [H-C102D102N]  15.9 37.7 0 top
HOLE24  *hg-c315d118p2  [HG-C315D118P2]  17.9 31.7 0 top
HOLE25  h-tc228ibc189d146p2  [H-TC228IBC189D146P2]  183 31.22 180 bottom
HOLE26  *HG-C276D118P2  [HG-C276D118P2]  284.1 25.1 0 top
HOLE27  -  [H-TC228BC181D138P2]  273.2 18.7 180 bottom
HOLE28  *hg-tic315bc394d118p2  [HG-TIC315BC394D118P2]  44.9 11.85 0 top
HOLE29  *hg-c315d118p2  [HG-C315D118P2]  96.9 11.85 0 top
HOLE30  *H-TIC220BC283D146P2  [H-TIC220BC283D146P2]  165 99 0 top
HOLE31  *2D-BARCODE-8X8-S  [2D-BARCODE-8X8-S]  162.07 171.36 180 bottom
J1  *SHORT_PAD  [JOPEN25X30_S]  184.32 37.48 270 bottom
JDIM1  DDR4-DIMM0_H=5.2_RVS  [DDR4-D4AR0-26001-1P52-RVS-SMT]  139.7 54.3 0 top
JDIM2  DDR3-DIMM0_H=9.2_RVS  [DDR4-D4AR0-26001-1P92-RVS-260P]  139.7 41.3 0 top
JDIM3  DDR4-DIMM0_H=4_STD  [DDR4-D4AS0-26001-1P40-STD-SMT]  137.8 54.4 180 bottom
JDIM4  DDR3-DIMM0_H=4_RVS  [DDR4-D4AR0-26001-1P40-RVS-SMT]  137.8 41.4 0 bottom
L1  0.68uH_2.5x2.0x1.2  [L2_5X2-1_2H]  273.45 56.56 0 top
L2  PBY160808T-600Y-N  [R0603]  30.63 38.37 0 top
L3  PBY160808T-600Y-N  [R0603]  34.12 38.26 180 top
L4  BLM15AG121SN1D  [R0402]  70.63 37.53 0 top
L5  3.3uH_3x3x1.5  [L3X3-1_6H]  268.37 34.84 0 top
L6  *DLP11SN900HL2L  [CHOKE-DLP11SN900HL2L-4P-1]  284.5 33.45 0 top
L7  HCB2012KF-220T60  [R0805]  24.3 32.38 90 top
L8  PBY160808T-221Y-N  [R0603]  267.23 29.63 90 top
L9  PBY160808T-600Y-N  [R0603]  45.61 28.36 180 top
L10  PBY160808T-600Y-N  [R0603]  48.28 27.85 180 top
L11  PBY160808T-221Y-N  [R0603]  278.4 27.25 90 top
L12  PBY160808T-600Y-N  [R0603]  9.16 26.71 0 top
L13  BLM15AG121SN1D  [R0402]  88.61 26.23 0 top
L14  BLM15AG121SN1D  [R0402]  88.08 25.21 0 top
L15  PBY160808T-600Y-N  [R0603]  9.16 25.19 0 top
L16  PBY160808T-600Y-N  [R0603]  48.28 24.43 180 top
L17  3.3uH_3x3x1.5  [L3X3-1_6H]  273.2 24.38 0 top
L18  PBY160808T-600Y-N  [R0603]  48.28 22.9 180 top
L19  PBY160808T-600Y-N  [R0603]  9.29 22.11 0 top
L20  PBY160808T-600Y-N  [R0603]  9.29 20.59 0 top
L21  BLM18KG331SN1D  [R0603]  61.84 17.8 0 top
L22  PBY160808T-600Y-N  [R0603]  19.75 17.03 0 top
L23  PBY160808T-600Y-N  [R0603]  26.33 16.93 180 top
L24  PBY160808T-600Y-N  [R0603]  18.92 15.21 0 top
L25  PBY160808T-600Y-N  [R0603]  22.83 14.65 0 top
L26  PBY160808T-221Y-N  [R0603]  269.26 13 90 top
L27  PBY160808T-600Y-N  [R0603]  181.25 96.99 0 bottom
L28  1uH_0.7A_0603  [R0603]  271.67 56.3 90 bottom
L29  *PBY160808T-600Y-N  [R0603]  239.92 54.27 180 bottom
L30  *PBY160808T-600Y-N  [R0603]  239.92 52.49 180 bottom
L31  PBY160808T-600Y-N  [R0603]  239.92 50.84 180 bottom
L32  *MCM2012B900GBE  [FILTER-MCM2012B900GBE-4P]  203.27 43.3 270 bottom
L33  PBY160808T-221Y-N  [R0603]  266.97 33.19 90 bottom
L34  *DLP11SN900HL2L  [CHOKE-DLP11SN900HL2L-4P-1]  284.54 32.57 0 bottom
L35  BLM18KG331SN1D  [R0603]  61.66 30.32 90 bottom
L36  PBY160808T-221Y-N  [R0603]  268.88 25.19 0 bottom
L37  BLM18KG331SN1D  [R0603]  61.64 21 0 bottom
L39  BLM18KG331SN1D  [R0603]  270.34 12.22 270 bottom
L40  BLM18KG331SN1D  [R0603]  270.87 10 180 bottom
LED1  *White_19-113/T1D-CP2Q2HY/3T  [LED19-113-T1D-CP2Q2HY-3T]  166.82 117.71 180 top
LG1  HCB1005KF-330T30  [R0402]  27.43 104.28 90 top
LG2  HCB1005KF-330T30  [R0402]  25.19 101.41 90 bottom
NOREF  -  []  -2168.04 -2165.98 0 top
NOREF#2  -  []  -2168.04 -2165.98 0 top
NOREF#3  -  []  206.88 59.25 0 top
NOREF#4  -  [unnamed#2]  283.61 3.65 0 top
NOREF#5  -  []  -2168.04 -2165.98 0 top
NOREF#6  -  []  -2168.04 -2165.98 0 top
NOREF#7  -  []  -2168.04 -2165.98 0 top
NOREF#8  -  [unnamed#2]  16.02 19.98 0 top
NOREF#9  -  [unnamed#2]  168.29 173.7 0 top
NOREF#10  -  []  4.84 -51.52 0 top
NOREF#11  -  []  -2168.04 -2165.98 0 top
NOREF#12  -  []  -2168.04 -2165.98 0 top
NOREF#13  -  []  -2168.04 -2165.98 0 top
NOREF#14  -  []  169.94 -43.9 0 top
NOREF#15  -  [unnamed#2]  168.29 173.7 180 bottom
NOREF#16  -  []  147.95 172.84 180 bottom
NOREF#17  -  [unnamed#2]  283.61 3.65 180 bottom
NOREF#18  -  [unnamed#2]  16.02 19.98 180 bottom
PC1  *EV@2200p/50V_4  [C0402]  37.99 173.45 180 top
PC2  *EV@820p/50V_4  [C0402]  14.65 172.97 270 top
PC3  EV@0.22u/25V_4  [C0402]  15.79 172.86 270 top
PC4  4700p/50V_4  [C0402]  177.62 173.68 180 top
PC5  47p/50V_2  [C0201]  173.53 173.47 270 top
PC6  1000p/50V_2  [C0201]  172.54 172.97 270 top
PC7  0.01u/50V_4  [C0402]  174.62 172.86 90 top
PC8  2200p/50V_4  [C0402]  175.69 172.86 90 top
PC9  0.012u/25V_4  [C0402]  177.62 172.69 0 top
PC10  EV@2.2u/10V_4  [C0402]  18.43 170.6 180 top
PC11  1000p/50V_2  [C0201]  172.54 171.92 270 top
PC12  1000p/50V_2  [C0201]  173.4 171.8 0 top
PC13  33u/25V_D7H3  [ECAP7X3_5-7_2]  147.16 171.26 0 top
PC14  1000p/50V_2  [C0201]  170.96 170.48 270 top
PC15  1000p/50V_2  [C0201]  172.5 170.47 270 top
PC16  EV@0.1u/50V_4  [C0402]  18.46 168.72 0 top
PC17  EV@100p/50V_4  [C0402]  7.84 168.37 0 top
PC18  470p/50V_4  [C0402]  170.73 169.38 180 top
PC19  *EV@56p/25V_2  [C0201]  11.52 167.55 180 top
PC20  EV@330u/2V_7343H1.9  [CC7343]  39.51 168.19 90 top
PC21  EV@0.1u/25V_4  [C0402]  7.84 167.38 0 top
PC22  2200p/50V_4  [C0402]  169.77 168.37 0 top
PC23  *EV@56p/25V_2  [C0201]  11.6 166.69 90 top
PC24  EV@2200p/50V_4  [C0402]  18.28 166.49 0 top
PC25  47p/50V_4  [C0402]  171.16 167.96 90 top
PC26  *EV@33p/50V_2  [C0201]  12.74 166.08 180 top
PC27  EV@0.22u/25V_4  [C0402]  16.02 165.62 0 top
PC28  EV@0.1u/50V_4  [C0402]  18.26 165.4 0 top
PC29  *EV@56p/25V_2  [C0201]  11.42 165.01 0 top
PC30  *EV@1000p/16V_2  [C0201]  12.49 164.63 0 top
PC31  0.22u/25V_6  [C0603]  162.2 166.03 90 top
PC32  0.22u/25V_6  [C0603]  141.6 166.01 90 top
PC33  *EV@0.1u/25V_2  [C0201]  10.41 166.62 0 top
PC34  0.22u/25V_6  [C0603]  151.5 165.95 90 top
PC35  1200p/50V_4  [C0402]  170.12 165.95 270 top
PC36  470p/50V_4  [C0402]  171.16 165.95 90 top
PC37  0.22u/25V_6  [C0603]  131.34 165.85 90 top
PC38  EV@1u/25V_4  [C0402]  7.41 165.32 0 top
PC39  2.2u/10V_4  [C0402]  164.92 165.62 270 top
PC40  2.2u/10V_4  [C0402]  144.32 165.6 270 top
PC41  2.2u/10V_4  [C0402]  154.12 165.55 270 top
PC42  2.2u/10V_4  [C0402]  134.03 165.42 270 top
PC43  *EV@56p/25V_2  [C0201]  12.54 163.77 270 top
PC44  2200p/50V_4  [C0402]  139.85 164.76 270 top
PC45  0.1u/50V_4  [C0402]  129.38 164.96 270 top
PC46  2200p/50V_4  [C0402]  149.73 164.94 270 top
PC47  2200p/50V_4  [C0402]  160.42 164.89 270 top
PC48  0.1u/50V_4  [C0402]  117.31 164.82 0 top
PC49  EV@10u/25V_6  [C0603]  18.33 164.15 0 top
PC50  0.1u/50V_4  [C0402]  171.34 164.15 90 top
PC51  EV@0.1u/50V_4  [C0402]  7.05 163.62 270 top
PC52  EV@0.1u/50V_4  [C0402]  8.02 163.62 270 top
PC53  EV@2200p/50V_4  [C0402]  13.89 163.36 270 top
PC54  0.1u/50V_4  [C0402]  171.16 162.78 180 top
PC55  0.1u/50V_4  [C0402]  139.85 161.87 90 top
PC56  10u/25V_6  [C0603]  149.4 162.02 90 top
PC57  10u/25V_6  [C0603]  129.41 161.94 90 top
PC58  0.1u/50V_4  [C0402]  171.14 161.76 180 top
PC59  10u/25V_6  [C0603]  160.27 161.66 90 top
PC60  2.2u/10V_4  [C0402]  147.36 161.48 90 top
PC61  2.2u/10V_4  [C0402]  136.92 161.38 90 top
PC62  2.2u/10V_4  [C0402]  157.27 161.38 90 top
PC63  2.2u/10V_4  [C0402]  168.04 161.18 90 top
PC64  0.1u/50V_4  [C0402]  180.23 161.17 0 top
PC65  *2200p/50V_4  [C0402]  176.59 160.51 90 top
PC66  0.1u/50V_4  [C0402]  173.5 160.49 270 top
PC67  0.01u/50V_4  [C0402]  174.52 160.49 270 top
PC68  1u/6.3V_4  [C0402]  175.48 160.49 270 top
PC69  EV@10u/25V_6  [C0603]  18.92 159.96 90 top
PC70  22u/25V_8  [C0805]  101.59 158.96 0 top
PC71  0.1u/50V_4  [C0402]  126.97 158.32 180 top
PC72  1000p/50V_4  [C0402]  119.67 157.92 0 top
PC73  0.047u/50V_6  [C0603]  117.35 157.71 180 top
PC74  0.1u/25V_4  [C0402]  103.74 157.05 90 top
PC75  22u/25V_8  [C0805]  101.56 156.93 0 top
PC76  0.1u/10V_2  [C0201]  99.07 156.33 90 top
PC77  *EV@47u/6.3V_6  [C0603]  21.15 155.82 270 top
PC78  2.2u/10V_4  [C0402]  115.79 155.34 180 top
PC79  0.1u/25V_4  [C0402]  104.07 154.41 0 top
PC80  0.022u/25V_2  [C0201]  97.94 153.11 180 top
PC81  0.1u/25V_4  [C0402]  104.09 152.83 180 top
PC82  2.2u/10V_4  [C0402]  111.73 152.16 0 top
PC83  1u/6.3V_2  [C0201]  99.4 150.69 270 top
PC84  22u/25V_8  [C0805]  101.6 150.27 0 top
PC85  0.22u/25V_6  [C0603]  111.55 149.19 180 top
PC86  0.1u/25V_4  [C0402]  101.92 146.3 90 top
PC87  22u/25V_8  [C0805]  107.71 147.74 180 top
PC88  10u/25V_8  [C0805]  115.84 147.49 180 top
PC89  22u/6.3V_8  [C0805]  121.02 146.72 0 top
PC90  22u/6.3V_8  [C0805]  124.76 146.71 180 top
PC91  EV@47u/6.3V_6  [C0603]  12.68 138.94 0 top
PC92  *EV@47u/6.3V_6  [C0603]  20.08 146.51 90 top
PC93  0.1u/50V_4  [C0402]  174.52 145.84 90 top
PC94  10u/25V_8  [C0805]  115.85 145.46 180 top
PC95  *EV@2200p/50V_4  [C0402]  9.29 154.47 180 bottom
PC96  22u/6.3V_8  [C0805]  124.79 144.73 180 top
PC97  22u/6.3V_8  [C0805]  120.99 144.66 0 top
PC98  0.1u/50V_4  [C0402]  160.65 143.86 90 top
PC99  0.1u/50V_4  [C0402]  150.46 143.07 90 top
PC100  0.1u/50V_4  [C0402]  130.14 142.82 90 top
PC101  0.1u/50V_4  [C0402]  144.87 142.79 90 top
PC102  22u/6.3V_8  [C0805]  158.36 142.79 180 top
PC103  22u/6.3V_8  [C0805]  153.21 142.76 0 top
PC104  22u/6.3V_8  [C0805]  132.33 142.71 0 top
PC105  22u/6.3V_8  [C0805]  142.72 142.69 180 top
PC106  4.7u/25V_6  [C0603]  105.94 141.52 0 top
PC107  22u/6.3V_8  [C0805]  158.39 140.81 180 top
PC108  22u/6.3V_8  [C0805]  153.21 140.76 0 top
PC109  22u/6.3V_8  [C0805]  132.3 140.73 0 top
PC110  22u/6.3V_8  [C0805]  142.72 140.68 180 top
PC111  0.1u/25V_4  [C0402]  105.56 140.25 0 top
PC112  EV@1000p/50V_4  [C0402]  19.88 96.75 180 top
PC113  EV@10u/6.3V_6  [C0603]  17.67 96.54 0 top
PC114  EV@0.1u/50V_4  [C0402]  90.9 95.06 90 top
PC115  EV@10u/6.3V_4  [C0402_2]  105 94.81 90 top
PC116  EV@0.1u/50V_4  [C0402]  106.09 94.81 90 top
PC117  EV@10u/6.3V_4  [C0402_2]  103.68 94.78 90 top
PC118  EV@0.1u/50V_4  [C0402]  18.08 94.73 90 top
PC119  EV@0.1u/50V_4  [C0402]  102.33 93.88 270 top
PC120  EV@1u/25V_4  [C0402]  18.15 92.88 270 top
PC121  EV@0.01u/50V_4  [C0402]  96.89 92.29 90 top
PC122  EV@0.1u/50V_4  [C0402]  95.32 92.1 180 top
PC123  EV@10u/6.3V_4  [C0402_2]  102.48 91.29 0 top
PC124  *EV@0.1u/50V_4  [C0402]  7.02 86.05 270 top
PC125  EV@330u/2V_7343H1.9  [CC7343]  64.71 82.85 90 top
PC126  EV@330u/2V_7343H1.9  [CC7343]  69.69 82.82 90 top
PC127  EV@330u/2V_7343H1.9  [CC7343]  74.9 82.74 90 top
PC128  EV@330u/2V_7343H1.9  [CC7343]  79.9 82.74 90 top
PC129  *EV@2200p/50V_4  [C0402]  12.21 81.96 0 top
PC130  EV@10u/6.3V_4  [C0402_2]  8.65 78.4 90 top
PC131  EV@0.01u/50V_4  [C0402]  9.75 78.4 90 top
PC132  4.7u/6.3V_6  [C0603]  96.74 76.32 180 top
PC133  *10u/6.3V_6  [C0603]  98.89 74.62 270 top
PC134  10u/6.3V_6  [C0603]  98.55 67.4 180 top
PC135  *0.47u/6.3V_4  [C0402]  94.91 69.64 0 top
PC136  0.1u/50V_4  [C0402]  99 69.18 180 top
PC137  EV@2200p/50V_4  [C0402]  71.39 61.64 270 top
PC138  EV@2200p/50V_4  [C0402]  81.04 61.64 270 top
PC139  G3@2200p/50V_4  [C0402]  32.66 61.51 270 top
PC140  EV@2200p/50V_4  [C0402]  42.31 61.51 270 top
PC141  EV@2200p/50V_4  [C0402]  61.61 61.51 270 top
PC142  G3@2200p/50V_4  [C0402]  23.01 61.38 270 top
PC143  EV@2200p/50V_4  [C0402]  51.96 61.38 270 top
PC144  EV@2200p/50V_4  [C0402]  90.88 61.95 180 top
PC145  0.1u/25V_2  [C0201]  94.76 59.6 0 top
PC146  0.1u/25V_2  [C0201]  95.65 59.6 270 top
PC147  G3@0.1u/50V_4  [C0402]  15.13 61.89 270 top
PC148  G3@0.1u/50V_4  [C0402]  24.38 58.92 0 top
PC149  EV@0.1u/50V_4  [C0402]  34.03 58.92 0 top
PC150  EV@0.1u/50V_4  [C0402]  43.68 58.92 0 top
PC151  EV@0.1u/50V_4  [C0402]  53.33 58.92 0 top
PC152  EV@0.1u/50V_4  [C0402]  62.99 58.92 0 top
PC153  EV@0.1u/50V_4  [C0402]  72.64 58.92 0 top
PC154  EV@0.1u/50V_4  [C0402]  82.29 58.92 0 top
PC155  22u/25V_8  [C0805]  220.49 58.94 90 top
PC156  0.1u/25V_2  [C0201]  94.01 58.58 90 top
PC157  G3@2200p/50V_4  [C0402]  13.1 60.9 180 top
PC158  0.01u/50V_4  [C0402]  91.18 58.46 90 top
PC159  0.1u/50V_4  [C0402]  239.29 58.21 90 top
PC160  G3@0.1u/50V_4  [C0402]  13.1 59.59 0 top
PC161  G3@2200p/50V_4  [C0402]  24.38 57.95 180 top
PC162  EV@2200p/50V_4  [C0402]  34.03 57.95 180 top
PC163  EV@2200p/50V_4  [C0402]  43.68 57.95 180 top
PC164  EV@2200p/50V_4  [C0402]  53.33 57.95 180 top
PC165  EV@2200p/50V_4  [C0402]  62.99 57.95 180 top
PC166  EV@2200p/50V_4  [C0402]  72.64 57.95 180 top
PC167  EV@2200p/50V_4  [C0402]  82.29 57.95 180 top
PC168  *2200p/50V_4  [C0402]  184.78 57.32 0 top
PC169  *100p/50V_2  [C0201]  99.54 54.65 90 top
PC170  2.2u/10V_4  [C0402]  91.33 56.18 270 top
PC171  G3@10u/25V_6  [C0603]  12.85 55.16 90 top
PC172  G3@10u/25V_6  [C0603]  14.37 55.16 90 top
PC173  G3@10u/25V_6  [C0603]  24.4 54.7 90 top
PC174  EV@10u/25V_6  [C0603]  34.05 55.03 90 top
PC175  EV@10u/25V_6  [C0603]  43.71 55.03 90 top
PC176  EV@10u/25V_6  [C0603]  53.36 55.03 90 top
PC177  EV@10u/25V_6  [C0603]  63.01 55.03 90 top
PC178  EV@10u/25V_6  [C0603]  72.66 55.03 90 top
PC179  EV@10u/25V_6  [C0603]  82.31 55.03 90 top
PC180  820p/50V_4  [C0402]  241.06 54.27 0 top
PC181  0.1u/50V_4  [C0402]  236.37 54.4 0 top
PC182  100p/50V_2  [C0201]  99.54 53.65 270 top
PC183  0.047u/50V_4  [C0402]  90.82 53.25 0 top
PC184  G3@0.1u/25V_6  [C0603]  15.57 53.08 180 top
PC185  EV@0.1u/50V_4  [C0402]  40.61 52.37 0 top
PC186  0.47u/25V_4  [C0402]  90.82 52.24 0 top
PC187  100p/50V_2  [C0201]  99.43 51.83 90 top
PC188  EV@0.1u/25V_4  [C0402]  38.53 52.06 90 top
PC189  *22u/25V_8  [C0805]  63.65 51.98 270 top
PC190  *22u/25V_8  [C0805]  65.8 51.98 270 top
PC191  22u/25V_8  [C0805]  68.09 51.98 270 top
PC192  22u/25V_8  [C0805]  70.63 51.98 270 top
PC193  *EV@0.015u/25V_4  [C0402]  33.95 51.81 90 top
PC194  EV@0.015u/25V_4  [C0402]  37.03 51.6 180 top
PC195  2200p/50V_4  [C0402]  72.15 51.6 270 top
PC196  0.1u/50V_4  [C0402]  92.24 50.86 0 top
PC197  *EV@1000p/50V_2  [C0201]  36.72 50.51 270 top
PC198  EV@1u/6.3V_2  [C0201]  47.01 50.46 90 top
PC199  0.1u/50V_4  [C0402]  90.76 50.31 90 top
PC200  0.1u/50V_4  [C0402]  92.55 49.89 180 top
PC201  EV@33u/25V_D6.3H4.5  [ECAP6_3X7_7-7_8]  57.96 49.37 90 top
PC202  *EV@0.1u/25V_2  [C0201]  34.05 48.94 180 top
PC203  EV@220p/50V_2  [C0201]  46.81 48.78 0 top
PC204  *EV@0.015u/25V_4  [C0402]  36.11 48.33 90 top
PC205  *EV@0.1u/25V_2  [C0201]  35.07 48.3 180 top
PC206  EV@220p/50V_2  [C0201]  46.81 47.06 0 top
PC207  *680p/50V_6  [C0603]  83.97 46.78 0 top
PC208  EV@220p/50V_2  [C0201]  46.81 46.19 0 top
PC209  *0.01u/50V_4  [C0402]  63.9 46.09 90 top
PC210  EV@220p/50V_2  [C0201]  46.81 45.33 0 top
PC211  0.1u/50V_4  [C0402]  61.06 44.96 0 top
PC212  EV@220p/50V_2  [C0201]  46.81 44.47 0 top
PC213  EV_SP@220p/50V_2  [C0201]  46.81 43.73 0 top
PC214  680p/50V_4  [C0402]  58.9 43.37 180 top
PC215  EV_SP@220p/50V_2  [C0201]  46.81 42.99 0 top
PC216  1000p/50V_4  [C0402]  58.9 42.36 0 top
PC217  *EV@0.047u/25V_4  [C0402]  29.73 42.24 270 top
PC218  0.1u/50V_4  [C0402]  69.94 41.82 180 top
PC219  10u/25V_8  [C0805]  74.44 41.82 0 top
PC220  EV@4.7u/6.3V_2  [C0201]  44.99 41.6 0 top
PC221  EV@4700p/50V_4  [C0402]  33.67 41.44 90 top
PC222  2200p/50V_4  [C0402]  58.9 41.37 0 top
PC223  EV@1u/10V_2  [C0201]  37.46 40.96 270 top
PC224  2200p/50V_4  [C0402]  75.08 40.33 0 top
PC225  *EV@1500p/50V_4  [C0402]  35.96 39.67 0 top
PC226  EV@1000p/50V_2  [C0201]  44.6 38.71 90 top
PC227  EV@1000p/50V_2  [C0201]  42.12 38.27 90 top
PC228  EV@2.2u/10V_4  [C0402]  40.05 35.27 0 top
PC229  EV@0.015u/25V_4  [C0402]  40.02 31.16 180 top
PC230  0.1u/50V_4  [C0402]  147.23 30.87 270 top
PC231  0.01u/50V_4  [C0402]  170.3 30.43 270 top
PC232  22u/6.3V_8  [C0805]  149.54 30.16 180 top
PC233  10u/6.3V_4  [C0402_2]  172.53 29.76 180 top
PC234  10u/6.3V_4  [C0402_2]  92.14 28.36 0 top
PC235  220u/6.3V_D6.3H4.2  [ECAP6_3X7_7-7_8]  102.76 28.24 270 top
PC236  33u/25V_D6.3H4.5  [ECAP6_3X7_7-7_8]  110 28.24 270 top
PC237  22u/6.3V_8  [C0805]  149.54 28.17 180 top
PC238  *0.1u/50V_4  [C0402]  157.57 27.83 270 top
PC239  *0.1u/50V_4  [C0402]  155.47 27.8 270 top
PC240  1u/25V_4  [C0402]  94.64 27.74 0 top
PC241  22u/6.3V_6  [C0603]  164.09 27.77 0 top
PC242  0.1u/50V_4  [C0402]  92.14 27.12 0 top
PC243  0.1u/50V_4  [C0402]  175.98 27.1 270 top
PC244  220u/6.3V_D6.3H4.2  [ECAP6_3X7_7-7_8]  139.79 27.04 270 top
PC245  *0.1u/50V_4  [C0402]  97.58 27.02 180 top
PC246  0.1u/50V_4  [C0402]  160.55 26.93 270 top
PC247  4.7u/6.3V_2  [C0201]  121.23 26.81 90 top
PC248  33u/25V_D6.3H4.5  [ECAP6_3X7_7-7_8]  128.24 26.64 270 top
PC249  1000p/50V_2  [C0201]  92.5 26.28 180 top
PC250  22u/6.3V_8  [C0805]  149.55 26.18 180 top
PC251  0.1u/50V_4  [C0402]  97.58 26.03 180 top
PC252  1000p/50V_2  [C0201]  92.5 25.57 180 top
PC253  1u/6.3V_2  [C0201]  176.4 25.37 0 top
PC254  10u/6.3V_4  [C0402_2]  92.16 24.55 0 top
PC255  *68p/50V_4  [C0402]  176.11 24.52 180 top
PC256  0.033u/16V_4  [C0402]  159.86 24.45 180 top
PC257  1u/6.3V_2  [C0201]  152.83 24.3 180 top
PC258  22u/6.3V_8  [C0805]  149.55 24.14 180 top
PC259  0.1u/50V_4  [C0402]  100.2 24.07 0 top
PC260  *0.1u/50V_4  [C0402]  97.58 24.04 180 top
PC261  0.1u/50V_4  [C0402]  92.16 23.41 0 top
PC262  1u/25V_4  [C0402]  94.3 23.35 0 top
PC263  0.1u/50V_4  [C0402]  124.22 23.16 180 top
PC264  0.1u/50V_4  [C0402]  116.48 23.13 0 top
PC265  *22p/50V_4  [C0402]  175.74 22.9 90 top
PC266  0.1u/50V_4  [C0402]  152.41 22.12 0 top
PC267  10u/6.3V_4  [C0402_2]  159.13 21.79 270 top
PC268  330u/2V_7343H1.9  [CC7343]  146.76 20.75 0 top
PC269  *10u/6.3V_6  [C0603]  154.91 20.14 0 top
PC270  *0.1u/50V_4  [C0402]  175.27 19.78 180 top
PC271  *2200p/50V_4  [C0402]  167.22 19.47 0 top
PC272  0.1u/50V_4  [C0402]  120.03 19.45 90 top
PC273  10u/6.3V_4  [C0402_2]  121.18 19.45 90 top
PC274  10u/25V_8  [C0805]  160.97 18.96 270 top
PC275  1u/10V_4  [C0402]  162.48 18.93 90 top
PC276  0.1u/50V_4  [C0402]  141.02 18.89 90 top
PC277  *680p/50V_6  [C0603]  100.48 18.84 0 top
PC278  0.1u/50V_4  [C0402]  163.72 18.91 270 top
PC279  0.1u/50V_4  [C0402]  179.29 17.53 180 top
PC280  2200p/50V_4  [C0402]  159.65 15.62 90 top
PC281  2200p/50V_4  [C0402]  118.64 13.88 90 top
PC282  2200p/50V_4  [C0402]  123.72 13.88 90 top
PC283  330u/2V_7343H1.9  [CC7343]  175.5 13.81 270 top
PC284  10u/25V_8  [C0805]  120.16 13.76 90 top
PC285  10u/25V_8  [C0805]  122.19 13.76 90 top
PC286  2200p/50V_4  [C0402]  159.34 13.64 180 top
PC287  0.1u/50V_4  [C0402]  159.34 12.59 180 top
PC288  10u/25V_8  [C0805]  155.68 12.09 180 top
PC289  0.1u/50V_4  [C0402]  159.34 11.5 180 top
PC290  10u/25V_8  [C0805]  155.66 10.09 180 top
PC291  *680p/50V_6  [C0603]  128.78 9.93 0 top
PC292  *680p/50V_6  [C0603]  163.42 9.79 0 top
PC293  *680p/50V_6  [C0603]  152.01 9.78 180 top
PC294  EV@10u/25V_8  [C0805]  24.45 173.14 180 bottom
PC295  1000p/50V_4  [C0402]  181.88 171.16 90 bottom
PC296  1000p/50V_2  [C0201]  174.21 169.66 90 bottom
PC297  *0.1u/25V_2  [C0201]  178.99 169.46 90 bottom
PC298  470p/50V_4  [C0402]  177.06 169.26 270 bottom
PC299  470p/50V_4  [C0402]  174.47 166.77 0 bottom
PC300  0.01u/50V_4  [C0402]  174.45 165.72 180 bottom
PC301  2200p/50V_4  [C0402]  125.93 165.13 180 bottom
PC302  10u/25V_6  [C0603]  140.15 164.96 270 bottom
PC303  2200p/50V_4  [C0402]  129.39 164.95 270 bottom
PC304  0.1u/50V_4  [C0402]  149.8 164.88 270 bottom
PC305  0.1u/50V_4  [C0402]  160.48 164.86 270 bottom
PC306  680p/50V_4  [C0402]  125.95 164.09 0 bottom
PC307  1000p/50V_4  [C0402]  125.96 163.07 180 bottom
PC308  10u/25V_8  [C0805]  139.62 162.02 90 bottom
PC309  10u/25V_8  [C0805]  129.1 161.99 90 bottom
PC310  10u/25V_8  [C0805]  149.55 161.94 90 bottom
PC311  10u/25V_8  [C0805]  160.32 161.89 90 bottom
PC312  EV@10u/25V_8  [C0805]  7.83 159.94 90 bottom
PC313  1000p/50V_4  [C0402]  133.19 158.77 270 bottom
PC314  1000p/50V_4  [C0402]  143.91 158.74 270 bottom
PC315  1000p/50V_4  [C0402]  154.48 158.72 270 bottom
PC316  1000p/50V_4  [C0402]  165.22 158.49 270 bottom
PC317  *EV@47u/6.3V_6  [C0603]  44.85 157.6 270 bottom
PC318  EV@47u/6.3V_6  [C0603]  54.91 155.95 0 bottom
PC319  2200p/50V_4  [C0402]  178.07 155.87 270 bottom
PC320  EV@330u/2V_7343H1.9  [CC7343]  15.46 153.69 180 bottom
PC321  1000p/50V_4  [C0402]  118.2 151.68 90 bottom
PC322  330u/2V_7343H1.9  [CC7343]  152.7 151.43 90 bottom
PC323  330u/2V_7343H1.9  [CC7343]  163.42 151.35 90 bottom
PC324  100u/16V_7343H1.9  [CC7343]  107.08 150.28 90 bottom
PC325  EV@330u/2V_7343H1.9  [CC7343]  15.63 148.97 180 bottom
PC326  2200p/50V_4  [C0402]  115.9 148.63 180 bottom
PC327  0.1u/50V_4  [C0402]  115.94 147.11 180 bottom
PC328  0.1u/50V_4  [C0402]  120.79 147 0 bottom
PC329  0.1u/10V_2  [C0201]  106.33 144.42 90 bottom
PC330  *EV@47u/6.3V_6  [C0603]  39.26 143.3 270 bottom
PC331  EV@330u/2V_7343H1.9  [CC7343]  100.86 133.26 0 bottom
PC332  330u/2V_7343H1.9  [CC7343]  150.21 121.66 0 bottom
PC333  330u/2V_7343H1.9  [CC7343]  150.21 116.93 0 bottom
PC334  *EV@0.1u/50V_4  [C0402]  20.18 93.66 270 bottom
PC335  EV@0.1u/50V_4  [C0402]  19 92.91 90 bottom
PC336  EV@0.1u/50V_4  [C0402]  8.38 90.44 0 bottom
PC337  EV@22u/6.3V_6  [C0603]  7.87 89.1 0 bottom
PC338  *EV@22p/50V_4  [C0402]  7.41 83.51 0 bottom
PC339  *EV@68p/50V_4  [C0402]  7.59 81.02 270 bottom
PC340  EV@1u/6.3V_2  [C0201]  6.88 79.06 180 bottom
PC341  EV@330u/2V_7343H1.9  [CC7343]  81.04 70.15 270 bottom
PC342  EV@330u/2V_7343H1.9  [CC7343]  71.52 70.15 270 bottom
PC343  EV@330u/2V_7343H1.9  [CC7343]  66.69 70.15 270 bottom
PC344  EV@330u/2V_7343H1.9  [CC7343]  61.87 70.15 270 bottom
PC345  G3@330u/2V_7343H1.9  [CC7343]  57.04 70.15 270 bottom
PC346  EV@330u/2V_7343H1.9  [CC7343]  52.22 70.15 270 bottom
PC347  EV@330u/2V_7343H1.9  [CC7343]  47.39 70.15 270 bottom
PC348  EV@330u/2V_7343H1.9  [CC7343]  42.56 70.15 270 bottom
PC349  G3@330u/2V_7343H1.9  [CC7343]  37.74 70.15 270 bottom
